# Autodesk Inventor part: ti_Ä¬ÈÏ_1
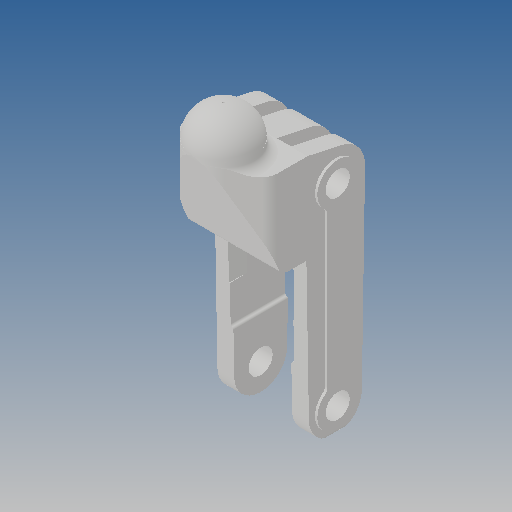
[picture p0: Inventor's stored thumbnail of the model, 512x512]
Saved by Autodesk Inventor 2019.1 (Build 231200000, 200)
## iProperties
Created: 2012-10
Part Number: ti_Ä¬ÈÏ_1
Material: Ogólny
Document SubType Name: Modeling
Designer: CADENGINEERING4
Density: 1 g/cm^3
Appearance: Domyślna
Author: CADENGINEERING4
Revision Number: ÈÎºÎ
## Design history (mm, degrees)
feature "NONE" [ÊäÈë]
feature "ÊäÈë2"
node "Bryła1"
node "Bryła2"
